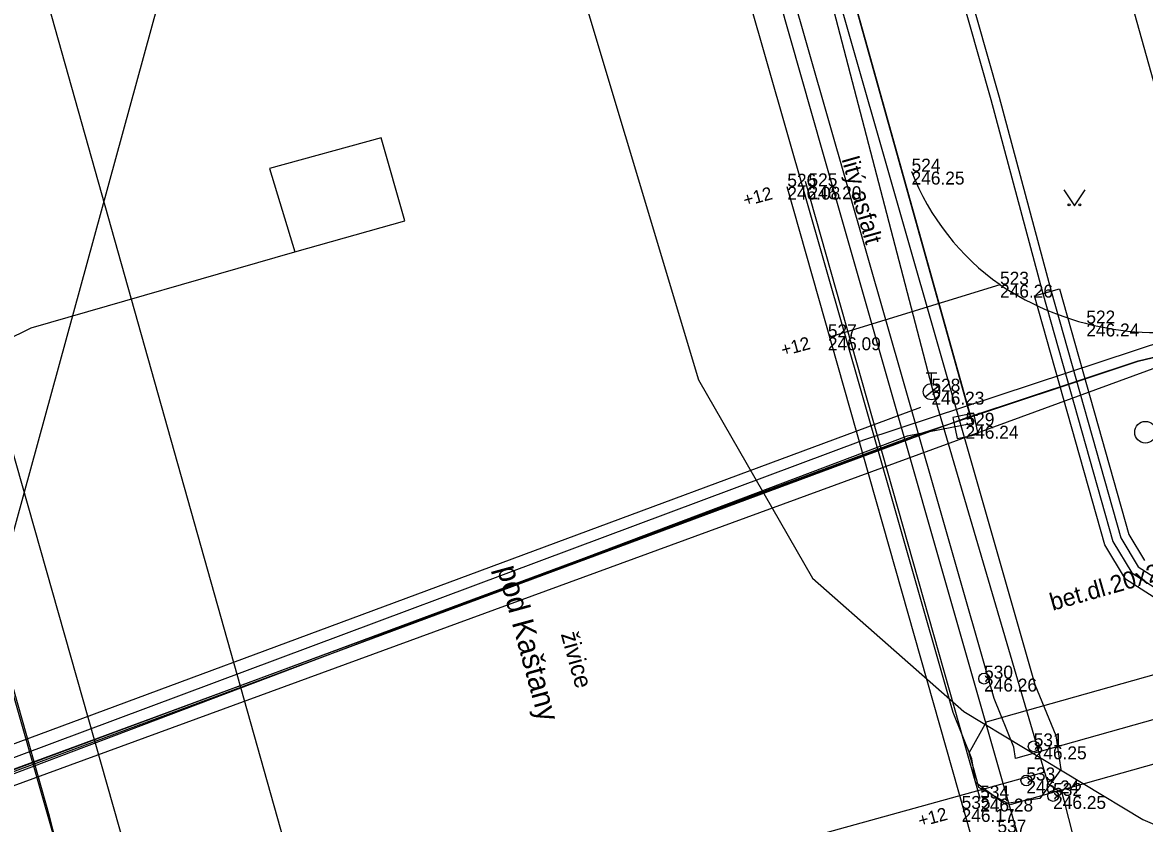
# Model space of a CAD drawing. Extents: x -599432 to -598680, y -1159407 to -1158632.
# Drawn here: x -599248.67 to -599222.66, y -1158937.41 to -1158918.84 of the extents above; entities that cross this region are included whole.
import ezdxf

# ---------------------------------------------------------------- set-up
doc = ezdxf.new("R2010")
doc.units = 0
for name, color, linetype in [('0004 VY - Body podrobné', 7, 'Continuous'), ('0005 VY - Body podrobné - čísla', 7, 'Continuous'), ('0006 VY - Body podrobné - výšky', 7, 'Continuous'), ('0027 ZA - Silnice_cesta zpevněná', 7, 'Continuous'), ('0030 ZA - Chodník', 7, 'Continuous'), ('0031 ZA - Ostatní rozhraní', 7, 'Continuous'), ('0032 TE - Popis povrchu', 7, 'Continuous'), ('0034 ZA - Kultury - značky', 7, 'Continuous'), ('0048 TE - Názvy ulic _ náměstí', 7, 'Continuous'), ('0071 ZA - Zábradlí', 7, 'Continuous'), ('0073 TE - Výška obrubníků a zdí', 7, 'Continuous'), ('0075 ZA - BVK - kanalizace - buňky', 7, 'Continuous'), ('0080 ZA - BVK - vodovod - buňky', 7, 'Continuous'), ('0092 ZA - RWE - plynovod - buňky', 7, 'Continuous'), ('0116 PV - budova převzatá z mapy', 7, 'Continuous'), ('0202 PV - MUNI', 7, 'Continuous'), ('0203 PV - MUNI - chránička', 7, 'Continuous'), ('0206 PV - BVK - kanalizace - jednotná', 7, 'Continuous'), ('0214 PV - BVK - vodovod - pitná', 7, 'Continuous'), ('0264 PV - TB - parovod mimo provoz', 7, 'Continuous'), ('0302 PV - RWE - NTL', 7, 'Continuous'), ('0308 PV - RWE - ochranné pásmo', 7, 'Continuous'), ('0354 PV - EON - VN', 7, 'Continuous'), ('0367 PV - EON - VN chránička', 7, 'Continuous'), ('0407 PV - TSB - kabelové vedení přibližný zákres', 7, 'Continuous'), ('0454 PV - O2 - kabel zaměřený', 7, 'Continuous'), ('0530 PV - T-mobile - optické kabely', 7, 'Continuous'), ('0552 PV - OT VUT', 7, 'Continuous'), ('0652 PV - BKOM - kabely bez rozlišení', 7, 'Continuous'), ('0704 PV - ČD - kabely', 7, 'Continuous'), ('0750 ZA - nerozlišené sítě - buňky', 7, 'Continuous')]:
    doc.layers.add(name, color=color, linetype=linetype)

msp = doc.modelspace()

# ---------------------------------------------------------------- linework, layer by layer
at = {"layer": '0004 VY - Body podrobné'}
for p, q in [((-599228.06, -1158922.3), (-599228.06, -1158922.3)), ((-599230.94, -1158922.65), (-599230.94, -1158922.65)), ((-599230.45, -1158922.64), (-599230.45, -1158922.64)), ((-599226.01, -1158924.92), (-599226.01, -1158924.92)), ((-599224.01, -1158925.82), (-599224.01, -1158925.82)), ((-599230, -1158926.14), (-599230, -1158926.14)), ((-599227.6, -1158927.4), (-599227.6, -1158927.4)), ((-599226.81, -1158928.19), (-599226.81, -1158928.19)), ((-599226.38, -1158934.05), (-599226.38, -1158934.05)), ((-599225.23, -1158935.62), (-599225.23, -1158935.62)), ((-599225.4, -1158936.41), (-599225.4, -1158936.41)), ((-599226.47, -1158936.83), (-599226.47, -1158936.83)), ((-599224.78, -1158936.77), (-599224.78, -1158936.77)), ((-599226.9, -1158937.07), (-599226.9, -1158937.07))]:
    msp.add_line(p, q, dxfattribs=at)
at = {"layer": '0027 ZA - Silnice_cesta zpevněná'}
msp.add_line((-599226.67, -1158937.72), (-599230.94, -1158922.65), dxfattribs=at)
at = {"layer": '0030 ZA - Chodník'}
for centre, radius, start, end in [((-599222.687, -1158920.208), 5.766, 201.2738, 234.8085), ((-599222.364, -1158919.49), 6.541, 236.121, 283.1121)]:
    msp.add_arc(centre, radius, start, end, dxfattribs=at)
at = {"layer": '0031 ZA - Ostatní rozhraní'}
msp.add_line((-599229.955, -1158926.126), (-599226.01, -1158924.92), dxfattribs=at)
at = {"layer": '0034 ZA - Kultury - značky'}
msp.add_lwpolyline([(-599224.535, -1158922.72), (-599224.285, -1158923.095), (-599224.035, -1158922.72)], dxfattribs=at)
for centre in [(-599224.41, -1158923.07), (-599224.16, -1158923.07)]:
    msp.add_circle(centre, 0.025, dxfattribs=at)
at = {"layer": '0071 ZA - Zábradlí'}
msp.add_line((-599226.47, -1158936.83), (-599230.521, -1158922.531), dxfattribs=at)
at = {"layer": '0075 ZA - BVK - kanalizace - buňky'}
msp.add_circle((-599222.64, -1158928.34), 0.25, dxfattribs=at)
at = {"layer": '0080 ZA - BVK - vodovod - buňky'}
for p, q in [((-599227.725, -1158926.962), (-599227.475, -1158926.962)), ((-599227.6, -1158927.212), (-599227.6, -1158926.962)), ((-599227.747, -1158927.516), (-599227.452, -1158927.284))]:
    msp.add_line(p, q, dxfattribs=at)
for centre, radius in [((-599227.6, -1158927.4), 0.188), ((-599225.23, -1158935.62), 0.125), ((-599225.4, -1158936.41), 0.125), ((-599224.78, -1158936.77), 0.125)]:
    msp.add_circle(centre, radius, dxfattribs=at)
at = {"layer": '0092 ZA - RWE - plynovod - buňky'}
msp.add_circle((-599226.38, -1158934.05), 0.125, dxfattribs=at)
at = {"layer": '0116 PV - budova převzatá z mapy'}
msp.add_line((-599220.88, -1158925.86), (-599226.34, -1158906.21), dxfattribs=at)
at = {"layer": '0202 PV - MUNI'}
msp.add_lwpolyline([(-599255.365, -1158936.128), (-599252.9, -1158935.879), (-599249.514, -1158936.12), (-599229.166, -1158928.515), (-599221.329, -1158925.93), (-599220.289, -1158926.362), (-599218.079, -1158932.75), (-599214.197, -1158932.926), (-599209.818, -1158931.805), (-599201.617, -1158928.611), (-599200.477, -1158928.983), (-599199.188, -1158931.945), (-599199.148, -1158932.658), (-599198.604, -1158933.738), (-599197.027, -1158935.771), (-599194.361, -1158937.172), (-599193.665, -1158937.164), (-599183.138, -1158934.154), (-599174.357, -1158932.265), (-599146.637, -1158922.988), (-599125.848, -1158917.745)], dxfattribs=at)
at = {"layer": '0203 PV - MUNI - chránička'}
for p, q in [((-599249.618, -1158935.838), (-599227.844, -1158927.763)), ((-599249.41, -1158936.401), (-599227.635, -1158928.326))]:
    msp.add_line(p, q, dxfattribs=at)
at = {"layer": '0206 PV - BVK - kanalizace - jednotná'}
msp.add_lwpolyline([(-599243.198, -1158893.146), (-599232.997, -1158927.127), (-599230.359, -1158931.723), (-599226.848, -1158934.811), (-599222.704, -1158937.313), (-599218.632, -1158939.061), (-599216.024, -1158939.496), (-599214.704, -1158939.667)], dxfattribs=at)
at = {"layer": '0214 PV - BVK - vodovod - pitná'}
for p, q in [((-599225.131, -1158935.69), (-599224.977, -1158936.218)), ((-599224.977, -1158936.218), (-599225.27, -1158936.3))]:
    msp.add_line(p, q, dxfattribs=at)
for points in [[(-599235.388, -1159041.29), (-599254.88, -1158972.58), (-599257.33, -1158961.51), (-599240.44, -1158899.85), (-599263.133, -1158825.464)], [(-599248.63, -1158852.071), (-599247.311, -1158857.5), (-599242.826, -1158873.819), (-599235.069, -1158899.674), (-599234.747, -1158900.7), (-599230.149, -1158917.475), (-599227.55, -1158927.44), (-599225.131, -1158935.689)], [(-599224.534, -1158936.87), (-599222.42, -1158945.16), (-599215.18, -1158973.1), (-599214.01, -1158973.78), (-599152.34, -1158956.416), (-599150.65, -1158955.95), (-599117.576, -1158946.804), (-599098.24, -1158941.96), (-599043.28, -1158926.64)], [(-599225.27, -1158936.3), (-599245.28, -1158941.84), (-599252.496, -1158943.801), (-599301.084, -1158957.01)], [(-599224.977, -1158936.218), (-599224.895, -1158936.488), (-599224.58, -1158936.7), (-599224.534, -1158936.871)]]:
    msp.add_lwpolyline(points, dxfattribs=at)
at = {"layer": '0264 PV - TB - parovod mimo provoz'}
msp.add_lwpolyline([(-599164.247, -1158923.62), (-599240.684, -1158944.621), (-599259.43, -1158878.076)], dxfattribs=at)
at = {"layer": '0302 PV - RWE - NTL'}
for points in [[(-599225.65, -1158935.9), (-599225.69, -1158935.64), (-599226.15, -1158934.51), (-599228.22, -1158927.27), (-599231.77, -1158914.86), (-599236.13, -1158899.14), (-599241.672, -1158879.669)], [(-599042.76, -1158885.49), (-599068.42, -1158892.17), (-599094.54, -1158899.36), (-599103.01, -1158901.75), (-599109.28, -1158903.4), (-599121.29, -1158906.57), (-599128.03, -1158908.44), (-599139.52, -1158911.687), (-599140.38, -1158911.93), (-599166.16, -1158919.18), (-599194.33, -1158927.1), (-599199.24, -1158928.46), (-599225.65, -1158935.9)]]:
    msp.add_lwpolyline(points, dxfattribs=at)
at = {"layer": '0308 PV - RWE - ochranné pásmo'}
msp.add_lwpolyline([(-599237.093, -1158899.411), (-599242.648, -1158879.89), (-599240.695, -1158879.448), (-599235.167, -1158898.869), (-599230.807, -1158914.589), (-599227.259, -1158926.995), (-599225.203, -1158934.183), (-599224.719, -1158935.372), (-599224.662, -1158935.748), (-599224.599, -1158936.157), (-599225.089, -1158936.825), (-599225.498, -1158936.888), (-599225.907, -1158936.951), (-599226.575, -1158936.461), (-599226.638, -1158936.052), (-599226.661, -1158935.908), (-599227.097, -1158934.837), (-599229.181, -1158927.545), (-599232.733, -1158915.131)], close=True, dxfattribs=at)
msp.add_lwpolyline([(-599140.109, -1158912.892), (-599165.889, -1158920.143), (-599194.061, -1158928.063), (-599198.971, -1158929.423), (-599225.379, -1158936.863), (-599225.777, -1158936.975), (-599226.5, -1158936.57), (-599226.613, -1158936.171), (-599226.725, -1158935.773), (-599226.32, -1158935.05), (-599225.921, -1158934.937), (-599199.509, -1158927.497), (-599194.599, -1158926.137), (-599166.431, -1158918.217), (-599140.651, -1158910.968)], dxfattribs=at)
at = {"layer": '0354 PV - EON - VN'}
for points in [[(-599227.006, -1158917.879), (-599226.226, -1158920.627), (-599225.016, -1158925.127), (-599223.393, -1158930.87), (-599222.954, -1158931.602), (-599220.922, -1158932.906), (-599216.548, -1158935.368), (-599214.474, -1158936.465), (-599212.649, -1158936.84), (-599208.772, -1158936.77), (-599204.245, -1158936.139), (-599198.361, -1158935.128), (-599194.071, -1158934.198), (-599187.146, -1158933.007)], [(-599226.814, -1158917.821), (-599226.034, -1158920.573), (-599224.824, -1158925.073), (-599223.207, -1158930.79), (-599222.806, -1158931.458), (-599220.818, -1158932.734), (-599216.452, -1158935.192), (-599214.406, -1158936.275), (-599212.631, -1158936.64), (-599208.788, -1158936.57), (-599204.275, -1158935.941), (-599198.399, -1158934.932), (-599194.109, -1158934.002), (-599187.194, -1158932.813)]]:
    msp.add_lwpolyline(points, dxfattribs=at)
at = {"layer": '0367 PV - EON - VN chránička'}
for p, q in [((-599225.209, -1158925.182), (-599224.631, -1158925.018)), ((-599223.578, -1158930.95), (-599225.209, -1158925.182)), ((-599224.631, -1158925.018), (-599223.022, -1158930.71)), ((-599223.022, -1158930.71), (-599222.659, -1158931.315)), ((-599223.101, -1158931.745), (-599223.578, -1158930.95)), ((-599221.025, -1158933.077), (-599223.101, -1158931.745))]:
    msp.add_line(p, q, dxfattribs=at)
at = {"layer": '0407 PV - TSB - kabelové vedení přibližný zákres'}
for p, q in [((-599230.098, -1158921.906), (-599236.414, -1158899.793)), ((-599225.345, -1158938.543), (-599230.098, -1158921.906)), ((-599249.258, -1158927.516), (-599244.297, -1158944.978))]:
    msp.add_line(p, q, dxfattribs=at)
at = {"layer": '0454 PV - O2 - kabel zaměřený'}
for points in [[(-599255.37, -1158936.4), (-599252.41, -1158936.17), (-599251.87, -1158936.34), (-599250.28, -1158936.56), (-599249.45, -1158936.37), (-599227.97, -1158928.41), (-599227.45, -1158928.24), (-599222.81, -1158926.69), (-599221.09, -1158926.28), (-599220.22, -1158926.69), (-599218.9, -1158931.35), (-599218, -1158932.72), (-599214.12, -1158932.98)], [(-599249.45, -1158936.37), (-599227.97, -1158928.41)]]:
    msp.add_lwpolyline(points, dxfattribs=at)
at = {"layer": '0530 PV - T-mobile - optické kabely'}
for points in [[(-599232.719, -1158906.428), (-599226.699, -1158927.977)], [(-599222.808, -1158926.689), (-599221.091, -1158926.277)], [(-599226.699, -1158927.977), (-599222.808, -1158926.689)], [(-599226.699, -1158927.977), (-599249.451, -1158936.362)]]:
    msp.add_lwpolyline(points, dxfattribs=at)
at = {"layer": '0552 PV - OT VUT'}
for points in [[(-599242.08, -1158873.37), (-599239, -1158884.41), (-599236.84, -1158891.96), (-599236.29, -1158893.87), (-599235.74, -1158895.79), (-599232.73, -1158906.41), (-599230.2, -1158915.42), (-599229.63, -1158917.47), (-599229.08, -1158919.43), (-599226.65, -1158928.14)], [(-599226.65, -1158928.14), (-599228.16, -1158928.43), (-599249.44, -1158936.47), (-599250.73, -1158936.79)]]:
    msp.add_lwpolyline(points, dxfattribs=at)
at = {"layer": '0652 PV - BKOM - kabely bez rozlišení'}
msp.add_line((-599251.051, -1158926.871), (-599246.936, -1158941.202), dxfattribs=at)
for points in [[(-599236.58, -1158968.87), (-599236.64, -1158968.44), (-599245.16, -1158953.34), (-599246.71, -1158950.26), (-599245.97, -1158947.97), (-599245.84, -1158945.59), (-599246, -1158945.19), (-599248.04, -1158937.24), (-599251.02, -1158926.7), (-599253.56, -1158917.73), (-599252.05, -1158917.24)], [(-599249.073, -1158926.219), (-599248.46, -1158925.92), (-599242.35, -1158924.16), (-599239.8, -1158923.44), (-599240.35, -1158921.52), (-599242.94, -1158922.23), (-599242.35, -1158924.16)]]:
    msp.add_lwpolyline(points, dxfattribs=at)
at = {"layer": '0704 PV - ČD - kabely'}
msp.add_lwpolyline([(-599114.022, -1158914.733), (-599146.63, -1158923.02), (-599155.536, -1158926.021), (-599174.713, -1158932.481), (-599184.127, -1158934.514), (-599194.001, -1158937.403), (-599194.747, -1158937.133), (-599197.224, -1158935.816), (-599199.288, -1158932.926), (-599199.494, -1158931.958), (-599200.756, -1158929.108), (-599201.883, -1158928.791), (-599209.995, -1158931.998), (-599214.441, -1158933.077), (-599217.743, -1158932.664), (-599219.108, -1158931.045), (-599220.314, -1158926.664), (-599221.203, -1158926.41), (-599249.842, -1158936.887), (-599252.604, -1158936.443), (-599255.248, -1158936.617)], dxfattribs=at)
at = {"layer": '0750 ZA - nerozlišené sítě - buňky'}
for p, q in [((-599226.615, -1158927.895), (-599227.105, -1158927.995)), ((-599227.105, -1158927.995), (-599227.005, -1158928.485)), ((-599226.515, -1158928.385), (-599226.615, -1158927.895)), ((-599227.005, -1158928.485), (-599226.515, -1158928.385))]:
    msp.add_line(p, q, dxfattribs=at)

# ---------------------------------------------------------------- texts
at = {"layer": '0005 VY - Body podrobné - čísla'}
for s, p in [('524', (-599228.06, -1158922.3)), ('526', (-599230.94, -1158922.65)), ('525', (-599230.45, -1158922.64)), ('523', (-599226.01, -1158924.92)), ('522', (-599224.01, -1158925.82)), ('527', (-599230, -1158926.14)), ('528', (-599227.6, -1158927.4)), ('529', (-599226.81, -1158928.19)), ('530', (-599226.38, -1158934.05)), ('531', (-599225.23, -1158935.62)), ('533', (-599225.4, -1158936.41)), ('534', (-599226.47, -1158936.83)), ('532', (-599224.78, -1158936.77)), ('535', (-599226.9, -1158937.07)), ('537', (-599226.07, -1158937.62))]:
    msp.add_text(s, height=0.3, dxfattribs=at).set_placement(p)
at = {"layer": '0006 VY - Body podrobné - výšky'}
for s, p in [('246.25', (-599228.06, -1158922.6)), ('246.08', (-599230.94, -1158922.95)), ('246.20', (-599230.45, -1158922.94)), ('246.26', (-599226.01, -1158925.22)), ('246.24', (-599224.01, -1158926.12)), ('246.09', (-599230, -1158926.44)), ('246.23', (-599227.6, -1158927.7)), ('246.24', (-599226.81, -1158928.49)), ('246.26', (-599226.38, -1158934.35)), ('246.25', (-599225.23, -1158935.92)), ('246.24', (-599225.4, -1158936.71)), ('246.28', (-599226.47, -1158937.13)), ('246.25', (-599224.78, -1158937.07)), ('246.17', (-599226.9, -1158937.37))]:
    msp.add_text(s, height=0.3, dxfattribs=at).set_placement(p)
at = {"layer": '0032 TE - Popis povrchu'}
for s, rotation, p in [('litý asfalt', 285.8198, (-599229.684, -1158922.014)), ('bet.dl.20x20', 15.9454, (-599224.791, -1158932.48)), ('živice', 285.5236, (-599236.192, -1158933.018))]:
    msp.add_text(s, height=0.4, rotation=rotation, dxfattribs=at).set_placement(p)
at = {"layer": '0048 TE - Názvy ulic _ náměstí'}
msp.add_text('pod Kaštany', height=0.5, rotation=285.2857, dxfattribs=at).set_placement((-599237.671, -1158931.494))
at = {"layer": '0073 TE - Výška obrubníků a zdí'}
for p in [(-599231.917, -1158923.111), (-599231.04, -1158926.584), (-599227.861, -1158937.494)]:
    msp.add_text('+12', height=0.3, rotation=15.1896, dxfattribs=at).set_placement(p)

doc.saveas('drawing.dxf')
